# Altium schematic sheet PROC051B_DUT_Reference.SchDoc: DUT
size 431 x 279 mm; Date: Not shown in title block; ApprovedBy: Not shown in title block; CheckedBy: Not shown in title block; Author: Not shown in title block; CompanyName: Not shown in title block; Engineer: Not shown in title block; Organization: Not shown in title block; Address1: Not shown in title block; Address2: Not shown in title block; Address3: Not shown in title block; Address4: Not shown in title block; DocumentNumber: 2; Revision: Use project parameter SCH_Rev; SheetNumber: 2; SheetTotal: 16; PageSetup: Record=PageOptions¦CenterHorizontal=True¦CenterVertical=True¦PrintScale=1.00¦XCorrection=1.00¦YCorrection=1.00¦PrintKind=0¦BorderSize=5000000¦LeftOffset=0¦BottomOffset=0¦Orientation=2¦PaperLength=1000¦PaperWidth=1000¦Scale=100¦PaperSource=15¦PrintQuality=-3¦MediaType=1¦DitherType=10¦PrintScaleMode=1¦PaperKind=Letter¦PaperIndex=1
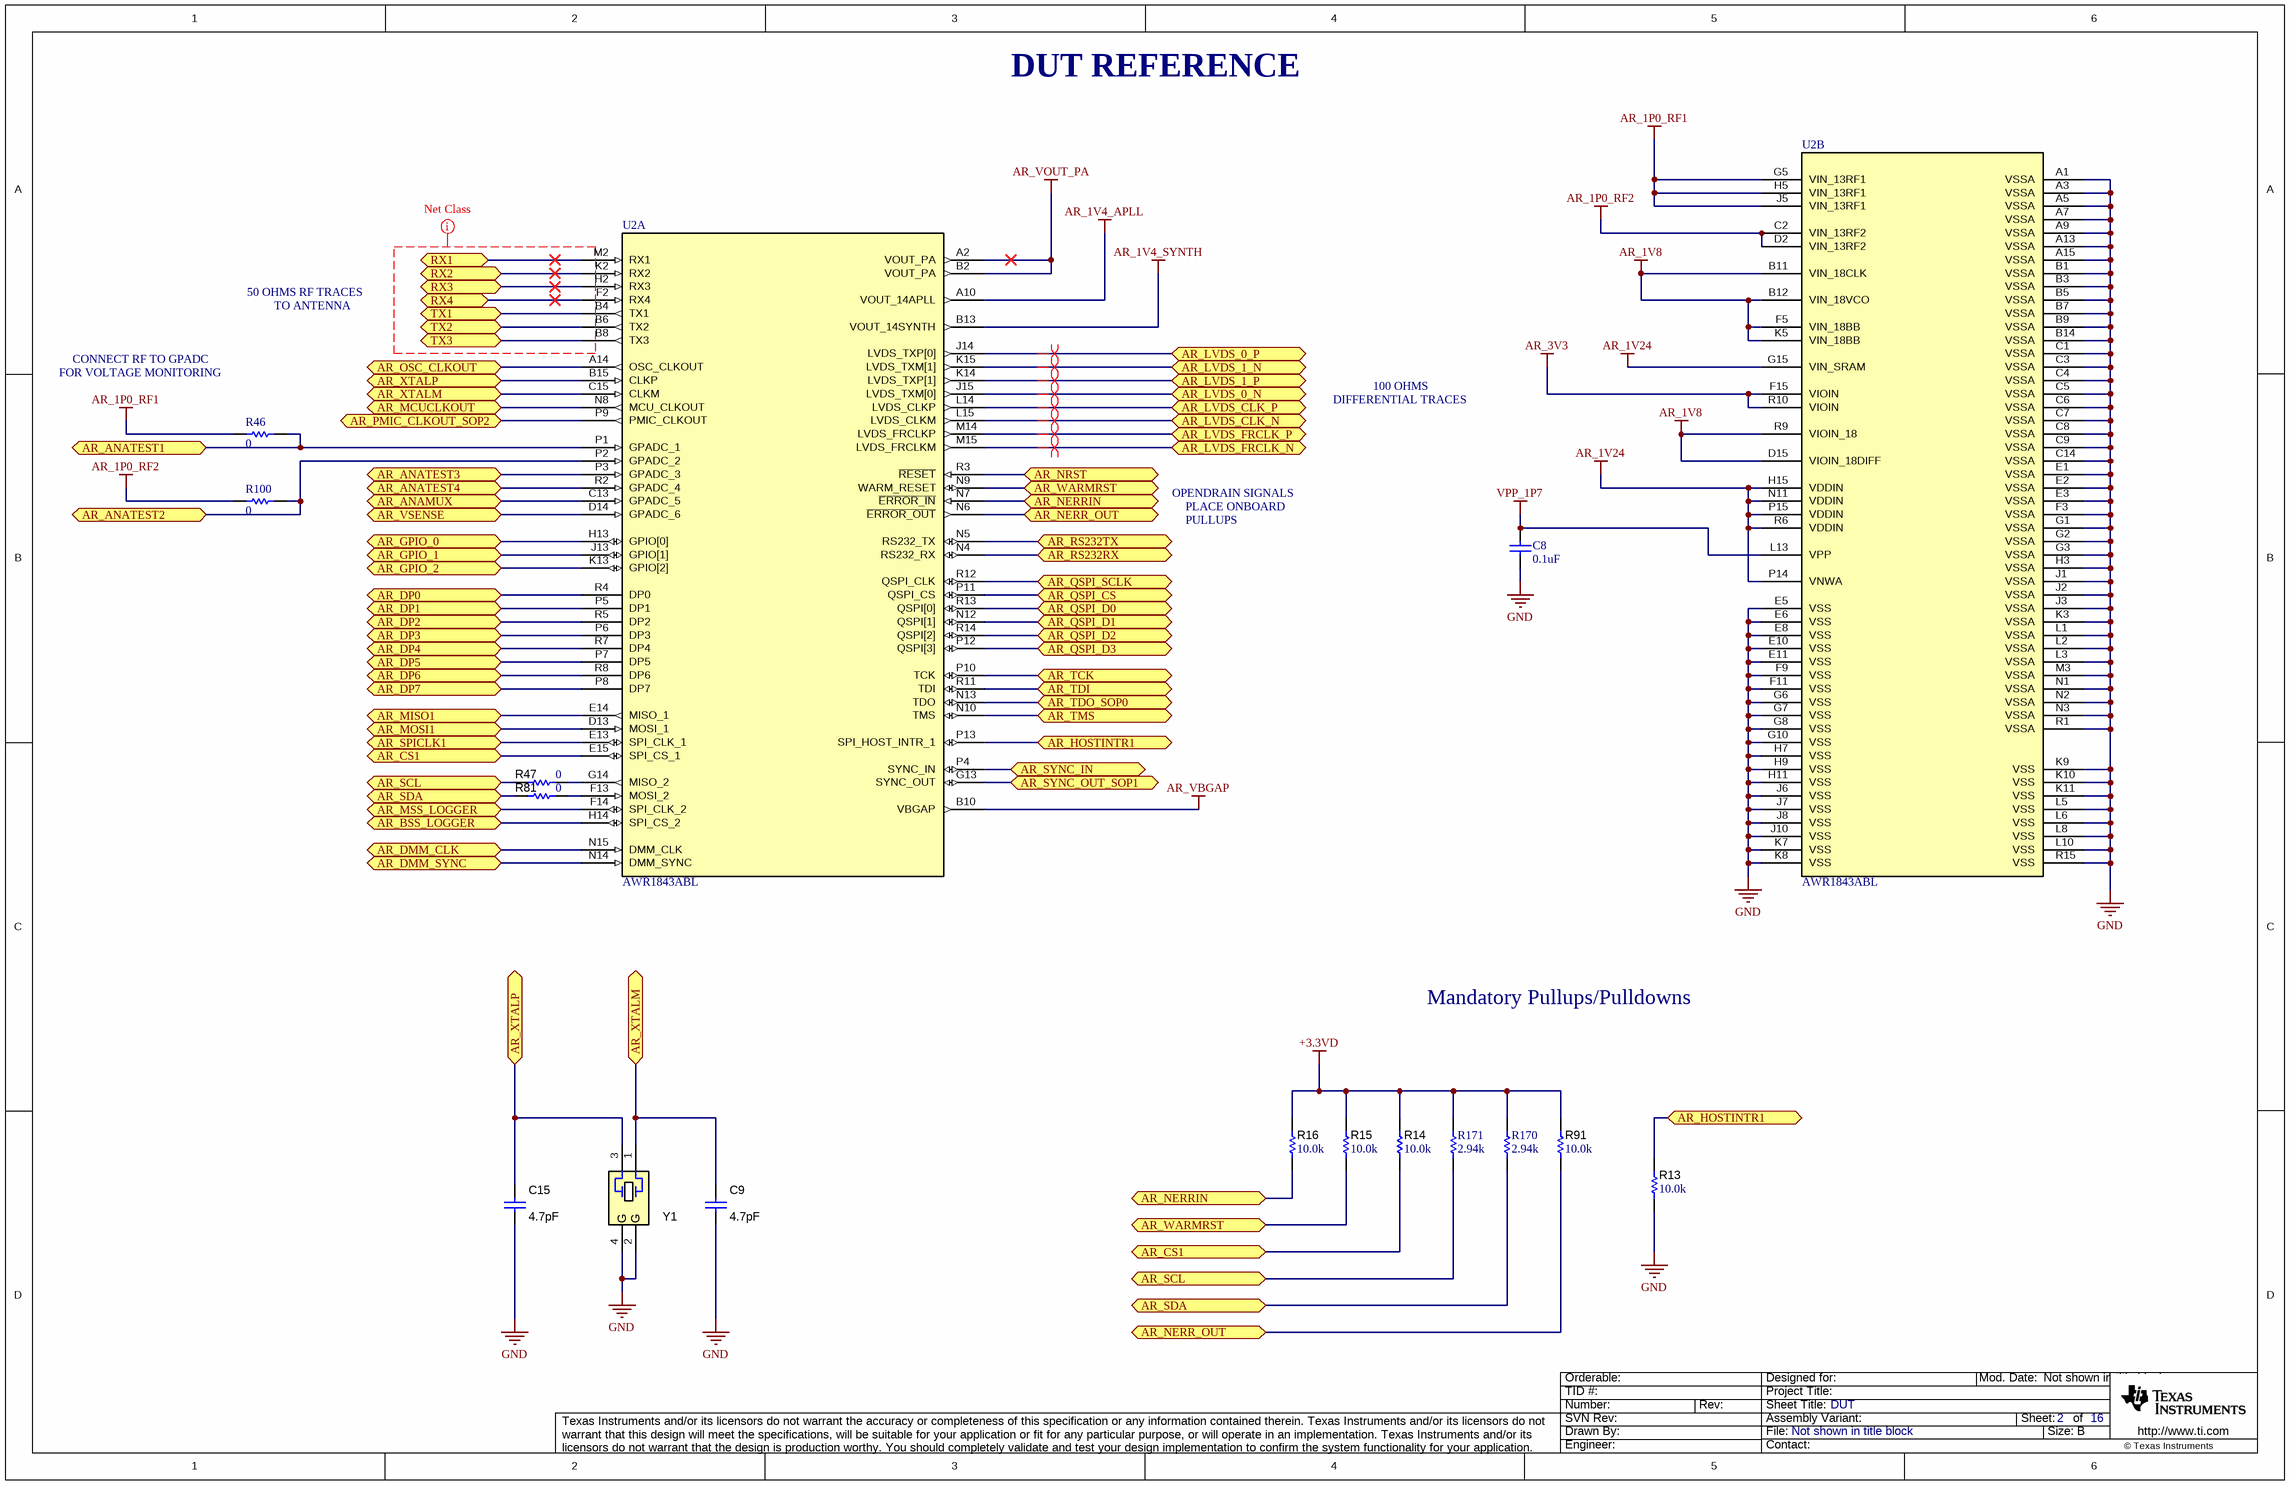
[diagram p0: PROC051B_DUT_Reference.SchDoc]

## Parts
C8  ValueDisplayed: 0.1uF  [0201]  (hidden comment: GRM033C71A104KE14D)
C9  ValueDisplayed: 4.7pF  [0402L]  (hidden comment: GJM1555C1H4R7BB01D)
C15  ValueDisplayed: 4.7pF  [0402L]  (hidden comment: GJM1555C1H4R7BB01D)
R13  ValueDisplayed: 10.0k  [0402L]  (hidden comment: CRCW040210K0FKED)
R14  ValueDisplayed: 10.0k  [0402L]  (hidden comment: CRCW040210K0FKED)
R15  ValueDisplayed: 10.0k  [0402L]  (hidden comment: CRCW040210K0FKED)
R16  ValueDisplayed: 10.0k  [0402L]  (hidden comment: CRCW040210K0FKED)
R46  ValueDisplayed: 0  [0402]  (hidden comment: CRCW04020000Z0ED)
R47  value 0  [0402L]  (hidden comment: Resistor)
R81  value 0  [0402L]  (hidden comment: Resistor)
R91  ValueDisplayed: 10.0k  [0402L]  (hidden comment: CRCW040210K0FKED)
R100  ValueDisplayed: 0  [0402]  (hidden comment: CRCW04020000Z0ED)
R170  ValueDisplayed: 2.94k  [0402]  (hidden comment: CRCW04022K94FKED)
R171  ValueDisplayed: 2.94k  [0402]  (hidden comment: CRCW04022K94FKED)
U2  AWR1843ABL  [ABL0161B]  (parts A,B of 2)
Y1  CX3225SA40000D0PTWCC  [Kyocera_CX3225SA]  (value not drawn)

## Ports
AR_ANAMUX, AR_ANATEST1, AR_ANATEST2, AR_ANATEST3, AR_ANATEST4, AR_BSS_LOGGER, AR_CS1, AR_DMM_CLK, AR_DMM_SYNC, AR_DP0, AR_DP1, AR_DP2, AR_DP3, AR_DP4, AR_DP5, AR_DP6, AR_DP7, AR_GPIO_0, AR_GPIO_1, AR_GPIO_2, AR_HOSTINTR1, AR_LVDS_0_N, AR_LVDS_0_P, AR_LVDS_1_N, AR_LVDS_1_P, AR_LVDS_CLK_N, AR_LVDS_CLK_P, AR_LVDS_FRCLK_N, AR_LVDS_FRCLK_P, AR_MCUCLKOUT, AR_MISO1, AR_MOSI1, AR_MSS_LOGGER, AR_NERR_OUT, AR_NERRIN, AR_NRST, AR_OSC_CLKOUT, AR_PMIC_CLKOUT_SOP2, AR_QSPI_CS, AR_QSPI_D0, AR_QSPI_D1, AR_QSPI_D2, AR_QSPI_D3, AR_QSPI_SCLK, AR_RS232RX, AR_RS232TX, AR_SCL, AR_SDA, AR_SPICLK1, AR_SYNC_IN, AR_SYNC_OUT_SOP1, AR_TCK, AR_TDI, AR_TDO_SOP0, AR_TMS, AR_VSENSE, AR_WARMRST, AR_XTALM, AR_XTALP, RX1, RX2, RX3, RX4, TX1, TX2, TX3

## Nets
+3.3VD: R14.2 R15.2 R16.2 R91.2 R170.2 R171.2
AR_1P0_RF1: R46.2 U2.G5(VIN_13RF1) U2.H5(VIN_13RF1) U2.J5(VIN_13RF1)
AR_1P0_RF2: R100.2 U2.C2(VIN_13RF2) U2.D2(VIN_13RF2)
AR_1V4_APLL: U2.A10(VOUT_14APLL)
AR_1V4_SYNTH: U2.B13(VOUT_14SYNTH)
AR_1V8: U2.B11(VIN_18CLK) U2.B12(VIN_18VCO) U2.D15(VIOIN_18DIFF) U2.F5(VIN_18BB) U2.K5(VIN_18BB) U2.R9(VIOIN_18)
AR_1V24: U2.G15(VIN_SRAM) U2.H15(VDDIN) U2.N11(VDDIN) U2.P14(VNWA) U2.P15(VDDIN) U2.R6(VDDIN)
AR_3V3: U2.F15(VIOIN) U2.R10(VIOIN)
AR_VBGAP: U2.B10(VBGAP)
AR_VOUT_PA: U2.A2(VOUT_PA) U2.B2(VOUT_PA)
GND: C8.2 C9.1 C15.1 R13.1 U2.A1(VSSA) U2.A3(VSSA) U2.A5(VSSA) U2.A7(VSSA) U2.A9(VSSA) U2.A13(VSSA) U2.A15(VSSA) U2.B1(VSSA) U2.B3(VSSA) U2.B5(VSSA) U2.B7(VSSA) U2.B9(VSSA) U2.B14(VSSA) U2.C1(VSSA) U2.C3(VSSA) U2.C4(VSSA) U2.C5(VSSA) U2.C6(VSSA) U2.C7(VSSA) U2.C8(VSSA) U2.C9(VSSA) U2.C14(VSSA) U2.E1(VSSA) U2.E2(VSSA) U2.E3(VSSA) U2.E5(VSS) U2.E6(VSS) U2.E8(VSS) U2.E10(VSS) U2.E11(VSS) U2.F3(VSSA) U2.F9(VSS) U2.F11(VSS) U2.G1(VSSA) U2.G2(VSSA) U2.G3(VSSA) U2.G6(VSS) U2.G7(VSS) U2.G8(VSS) U2.G10(VSS) U2.H3(VSSA) U2.H7(VSS) U2.H9(VSS) U2.H11(VSS) U2.J1(VSSA) U2.J2(VSSA) U2.J3(VSSA) U2.J6(VSS) U2.J7(VSS) U2.J8(VSS) U2.J10(VSS) U2.K3(VSSA) U2.K7(VSS) U2.K8(VSS) U2.K9(VSS) U2.K10(VSS) U2.K11(VSS) U2.L1(VSSA) U2.L2(VSSA) U2.L3(VSSA) U2.L5(VSS) U2.L6(VSS) U2.L8(VSS) U2.L10(VSS) U2.M3(VSSA) U2.N1(VSSA) U2.N2(VSSA) U2.N3(VSSA) U2.R1(VSSA) U2.R15(VSS) Y1.2(GND) Y1.4(GND)
VPP_1P7: C8.1 U2.L13(VPP)
AR_ANAMUX: U2.C13(GPADC_5) ; port AR_ANAMUX
AR_ANATEST1: R46.1 U2.P1(GPADC_1) ; port AR_ANATEST1
AR_ANATEST2: R100.1 U2.P2(GPADC_2) ; port AR_ANATEST2
AR_ANATEST3: U2.P3(GPADC_3) ; port AR_ANATEST3
AR_ANATEST4: U2.R2(GPADC_4) ; port AR_ANATEST4
AR_BSS_LOGGER: U2.H14(SPI_CS_2) ; port AR_BSS_LOGGER
AR_CS1: R14.1 U2.E15(SPI_CS_1) ; port AR_CS1
AR_DMM_CLK: U2.N15(DMM_CLK) ; port AR_DMM_CLK
AR_DMM_SYNC: U2.N14(DMM_SYNC) ; port AR_DMM_SYNC
AR_DP0: U2.R4(DP0) ; port AR_DP0
AR_DP1: U2.P5(DP1) ; port AR_DP1
AR_DP2: U2.R5(DP2) ; port AR_DP2
AR_DP3: U2.P6(DP3) ; port AR_DP3
AR_DP4: U2.R7(DP4) ; port AR_DP4
AR_DP5: U2.P7(DP5) ; port AR_DP5
AR_DP6: U2.R8(DP6) ; port AR_DP6
AR_DP7: U2.P8(DP7) ; port AR_DP7
AR_GPIO_0: U2.H13(GPIO[0]) ; port AR_GPIO_0
AR_GPIO_1: U2.J13(GPIO[1]) ; port AR_GPIO_1
AR_GPIO_2: U2.K13(GPIO[2]) ; port AR_GPIO_2
AR_HOSTINTR1: R13.2 U2.P13(SPI_HOST_INTR_1) ; port AR_HOSTINTR1
AR_LVDS_0_N: U2.J15(LVDS_TXM[0]) ; port AR_LVDS_0_N
AR_LVDS_0_P: U2.J14(LVDS_TXP[0]) ; port AR_LVDS_0_P
AR_LVDS_1_N: U2.K15(LVDS_TXM[1]) ; port AR_LVDS_1_N
AR_LVDS_1_P: U2.K14(LVDS_TXP[1]) ; port AR_LVDS_1_P
AR_LVDS_CLK_N: U2.L15(LVDS_CLKM) ; port AR_LVDS_CLK_N
AR_LVDS_CLK_P: U2.L14(LVDS_CLKP) ; port AR_LVDS_CLK_P
AR_LVDS_FRCLK_N: U2.M15(LVDS_FRCLKM) ; port AR_LVDS_FRCLK_N
AR_LVDS_FRCLK_P: U2.M14(LVDS_FRCLKP) ; port AR_LVDS_FRCLK_P
AR_MCUCLKOUT: U2.N8(MCU_CLKOUT) ; port AR_MCUCLKOUT
AR_MISO1: U2.E14(MISO_1) ; port AR_MISO1
AR_MOSI1: U2.D13(MOSI_1) ; port AR_MOSI1
AR_MSS_LOGGER: U2.F14(SPI_CLK_2) ; port AR_MSS_LOGGER
AR_NERR_OUT: R91.1 U2.N6(~{ERROR_OUT}) ; port AR_NERR_OUT
AR_NERRIN: R16.1 U2.N7(~{ERROR_IN}) ; port AR_NERRIN
AR_NRST: U2.R3(~{RESET}) ; port AR_NRST
AR_OSC_CLKOUT: U2.A14(OSC_CLKOUT) ; port AR_OSC_CLKOUT
AR_PMIC_CLKOUT_SOP2: U2.P9(PMIC_CLKOUT) ; port AR_PMIC_CLKOUT_SOP2
AR_QSPI_CS: U2.P11(QSPI_CS) ; port AR_QSPI_CS
AR_QSPI_D0: U2.R13(QSPI[0]) ; port AR_QSPI_D0
AR_QSPI_D1: U2.N12(QSPI[1]) ; port AR_QSPI_D1
AR_QSPI_D2: U2.R14(QSPI[2]) ; port AR_QSPI_D2
AR_QSPI_D3: U2.P12(QSPI[3]) ; port AR_QSPI_D3
AR_QSPI_SCLK: U2.R12(QSPI_CLK) ; port AR_QSPI_SCLK
AR_RS232RX: U2.N4(RS232_RX) ; port AR_RS232RX
AR_RS232TX: U2.N5(RS232_TX) ; port AR_RS232TX
AR_SCL: R47.2 R171.1 ; port AR_SCL
AR_SDA: R81.2 R170.1 ; port AR_SDA
AR_SPICLK1: U2.E13(SPI_CLK_1) ; port AR_SPICLK1
AR_SYNC_IN: U2.P4(SYNC_IN) ; port AR_SYNC_IN
AR_SYNC_OUT_SOP1: U2.G13(SYNC_OUT) ; port AR_SYNC_OUT_SOP1
AR_TCK: U2.P10(TCK) ; port AR_TCK
AR_TDI: U2.R11(TDI) ; port AR_TDI
AR_TDO_SOP0: U2.N13(TDO) ; port AR_TDO_SOP0
AR_TMS: U2.N10(TMS) ; port AR_TMS
AR_VSENSE: U2.D14(GPADC_6) ; port AR_VSENSE
AR_WARMRST: R15.1 U2.N9(WARM_RESET) ; port AR_WARMRST
AR_XTALM: C9.2 U2.C15(CLKM) Y1.1 ; port AR_XTALM
AR_XTALP: C15.2 U2.B15(CLKP) Y1.3 ; port AR_XTALP
RX1: U2.M2(RX1) ; port RX1
RX2: U2.K2(RX2) ; port RX2
RX3: U2.H2(RX3) ; port RX3
RX4: U2.F2(RX4) ; port RX4
TX1: U2.B4(TX1) ; port TX1
TX2: U2.B6(TX2) ; port TX2
TX3: U2.B8(TX3) ; port TX3
NetR47_1: R47.1 U2.G14(MISO_2)
NetR81_1: R81.1 U2.F13(MOSI_2)

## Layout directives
differential pair: AR_LVDS_0_N, AR_LVDS_0_P, AR_LVDS_1_N, AR_LVDS_1_P, AR_LVDS_CLK_N, AR_LVDS_CLK_P, AR_LVDS_FRCLK_N, AR_LVDS_FRCLK_P
net class RX_TX: (no net found under the mark)

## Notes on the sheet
- DUT REFERENCE
- 50 OHMS RF TRACES
- CONNECT RF TO GPADC
- TO ANTENNA
- FOR VOLTAGE MONITORING
- DIFFERENTIAL TRACES
- 100 OHMS
- OPENDRAIN SIGNALS
- PLACE ONBOARD
- PULLUPS
- Mandatory Pullups/Pulldowns

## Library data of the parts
C8 = CMP-0064969-1: CAP, CERM, 0.1 uF, 10 V,+/- 10%, X7S, 0201; Manufacturer: MuRata; TaMin_C: -55°C; Polarized: N; SizeAreaWB_mm2: 2.08; Value1: Unknown; U/M: EA; Value: 0.1uF; TaMax_C: 125°C; SizeZ_mm: 0.26; SizeX_mm: 0.6; SizeY_mm: 0.3; Value2: 10V; SizeArea_mm2: 0.18; CompType: Capacitor; Cap_F: 100nF; AEC Category: Q200
C9 C15 = CMP-0006367-2: CAP, CERM, 4.7 pF, 50 V, +/- 2%, C0G/NP0, 0402; Manufacturer: MuRata; TaMin_C: -55°C; Polarized: N; SizeAreaWB_mm2: 3; Value1: Unknown; U/M: EA; Value: 4.7pF; TaMax_C: 125°C; SizeZ_mm: 0.6; SizeX_mm: 1; SizeY_mm: 0.5; Cap_Case: 0402; Value2: 50V; CompType: Capacitor; AEC Category: Q200
R13-R16 R91 = CMP-0025958-3: RES, 10.0 k, 1%, 0.063 W, AEC-Q200 Grade 0, 0402; Manufacturer: Vishay-Dale; Power_W: 63mW; TempCo: 100 ppm/C; Value_Code: 10k0; Value: 10.0k; EIA_Code: E96; Res_ohm: 10k; SizeX_mm: 1; SizeY_mm: 0.5; SizeZ_mm: 0.6; Value2: 0.063W; AEC Qualified: Y; VDC_V: 50V; AEC Category: Q200; AEC Grade: 0
R46 R100 = CMP-0026822-3: RES, 0, 5%, 0.063 W, AEC-Q200 Grade 0, 0402; Manufacturer: Vishay-Dale; Power_W: 63mW; TempCo: 200 ppm/C; Value_Code: 0000; Value: 0; EIA_Code: E24; SizeX_mm: 1; SizeY_mm: 0.5; SizeZ_mm: 0.6; Value2: 0.063W; CompType: Resistor; AEC Qualified: Y; VDC_V: 50V; AEC Category: Q200
R47 R81 = CMP-0026822-3: RES, 0, 5%, 0.063 W, AEC-Q200 Grade 0, 0402; PartNumber: CRCW04020000Z0ED; Manufacturer: Vishay-Dale; Value_Code: 0000; Power_W: 63mW; Value2: 0.063W; VDC_V: 50V; TempCo: 200 ppm/C; EIA_Code: E24; AEC Category: Q200; AEC Qualified: Y; SizeArea_mm2: 0.5; SizeX_mm: 1; SizeZ_mm: 0.6
R170 R171 = CMP-0026244-2: RES, 2.94 k, 1%, 0.063 W, AEC-Q200 Grade 0, 0402; Manufacturer: Vishay-Dale; Power_W: 63mW; TempCo: 100 ppm/C; Value_Code: 2k94; Value: 2.94k; EIA_Code: E96; SizeX_mm: 1; SizeY_mm: 0.5; SizeZ_mm: 0.6; Value2: 0.063W; AEC Qualified: Y; VDC_V: 50V; AEC Category: Q200; AEC Grade: 0
U2 = CMP-0078239-1: AWR1843ABL, ABL0161B (FCBGA-161); Manufacturer: Texas Instruments; AEC Qualified: N; SizeArea_mm2: 108.16; CompType: IC; SizeAreaWB_mm2: 153.76; AEC Category: Q200; SizeY_mm: 10.4; SizeZ_mm: 1.17
Y1 = CMP-0004694-3: Crystal, 40 MHz, 8pF, SMD; Manufacturer: Kyocera; TaMin_C: -40°C; Frequency Stability: +/-200ppm; SizeAreaWB_mm2: 14.7; Frequency_Fixed: 40MHz; TaMax_C: 125°C; SizeZ_mm: 0.8; SizeX_mm: 2.5; SizeY_mm: 3.2; SizeArea_mm2: 8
